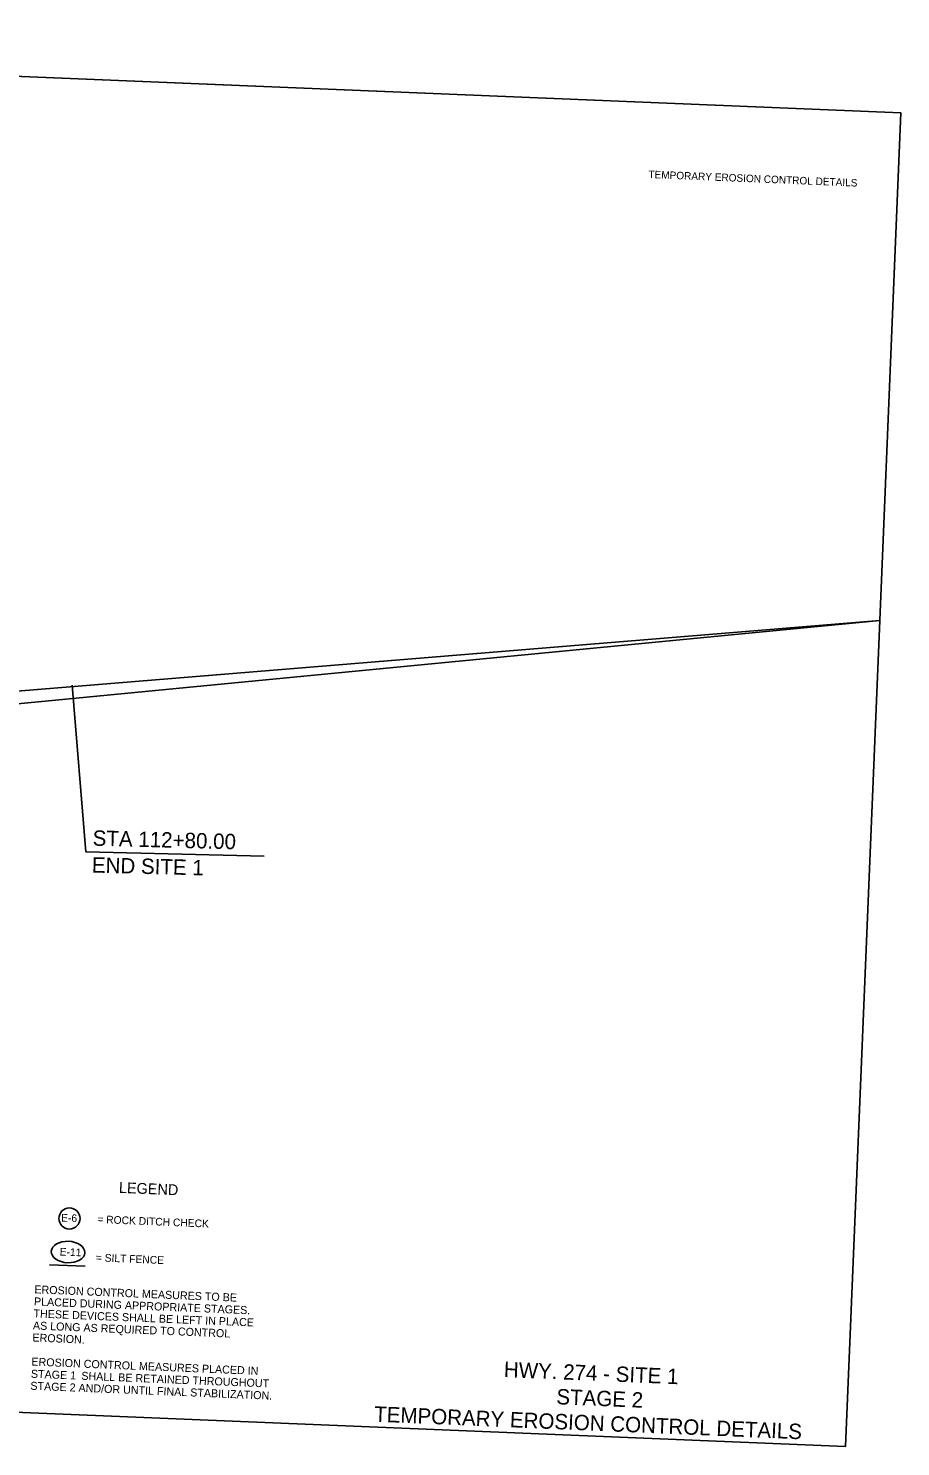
# Model space of a CAD drawing. Extents: x 1141828 to 1143465, y 1657046 to 1658153.
# Drawn here: x 1142784 to 1143465, y 1657046 to 1658153 of the extents above; entities that cross this region are included whole.
import ezdxf

# ---------------------------------------------------------------- set-up
doc = ezdxf.new("R2010")
doc.units = 0
for name, color, linetype in [('R_Annotation', 7, 'Continuous'), ('R_Border', 7, 'Continuous'), ('R_Erosion', 7, 'Continuous'), ('R_No Plot', 7, 'Continuous')]:
    doc.layers.add(name, color=color, linetype=linetype)

msp = doc.modelspace()

# ---------------------------------------------------------------- linework, layer by layer
at = {"layer": 'R_Annotation'}
for q in [(1142818.2, 1657640.2), (1142968, 1657506.6)]:
    msp.add_line((1142828.8, 1657510.1), q, dxfattribs=at)
at = {"layer": 'R_Erosion'}
msp.add_lwpolyline([(1142800.5, 1657187.6), (1142828.2, 1657186.5)], dxfattribs=at)
msp.add_circle((1142816, 1657223.8), 8.26, dxfattribs=at)
msp.add_ellipse((1142814.9, 1657197.6), major_axis=(13.1, -0.5), ratio=0.638788, dxfattribs=at)
at = {"layer": 'R_No Plot'}
for p, q in [((1143448.8, 1657690.7), (1142604.7, 1657621.7)), ((1143448.8, 1657690.6), (1142604.7, 1657621.6)), ((1143448.8, 1657690.7), (1142605.7, 1657609.2))]:
    msp.add_line(p, q, dxfattribs=at)
for points in [[(1141848.7, 1657609.9), (1141871.2, 1658153), (1143465.2, 1658087.1), (1143448.8, 1657690.7)], [(1142226.9, 1657603.3), (1142249.6, 1658137.4), (1143465.2, 1658087.1), (1143448.8, 1657690.7)], [(1141848.7, 1657609.8), (1141828.1, 1657111.6), (1143422.1, 1657045.7), (1143448.8, 1657690.6)]]:
    msp.add_lwpolyline(points, dxfattribs=at)

# ---------------------------------------------------------------- texts
at = {"layer": 'R_Annotation'}
for s, height, rotation, p in [('STA 112+80.00', 12, 358.5346, (1142834, 1657514.9)), ('END SITE 1', 12, 358.5346, (1142833.4, 1657493.9)), ('= ROCK DITCH CHECK', 6, 357.6311, (1142837.7, 1657220.3)), ('= SILT FENCE', 6, 357.6311, (1142836.5, 1657190.4)), ('EROSION CONTROL MEASURES TO BE', 6.25, 357.6311, (1142788.5, 1657165.4)), ('PLACED DURING APPROPRIATE STAGES. ', 6.25, 357.6311, (1142788.2, 1657156)), ('AS LONG AS REQUIRED TO CONTROL ', 6.25, 357.6311, (1142787.4, 1657137.2)), ('THESE DEVICES SHALL BE LEFT IN PLACE ', 6.25, 357.6311, (1142787.8, 1657146.6)), ('EROSION.', 6.25, 357.6311, (1142787, 1657127.8)), ('EROSION CONTROL MEASURES PLACED IN ', 6.25, 357.6311, (1142786.2, 1657109)), ('HWY. 274 - SITE 1', 12, 357.6311, (1143155.1, 1657100)), ('STAGE 1 ', 6.25, 357.6311, (1142785.8, 1657099.5)), ('SHALL BE RETAINED THROUGHOUT ', 6.25, 357.6311, (1142825.2, 1657097.9)), ('STAGE 2 AND/OR UNTIL FINAL STABILIZATION.', 6.25, 357.6311, (1142785.4, 1657090.1)), ('STAGE 2', 12, 357.6311, (1143196.1, 1657078.8)), ('TEMPORARY EROSION CONTROL DETAILS', 12, 357.6311, (1143053.8, 1657065.2))]:
    msp.add_text(s, height=height, rotation=rotation, dxfattribs=at).set_placement(p)
at = {"layer": 'R_Border'}
msp.add_text('TEMPORARY EROSION CONTROL DETAILS', height=5.862, rotation=357.6311, dxfattribs=at).set_placement((1143268.1, 1658036.2))
at = {"layer": 'R_Erosion'}
for s, height, rotation, p in [('LEGEND', 8.44, 357.6311, (1142854.5, 1657243.8)), ('E-6 ', 6, 358.0317, (1142809.4, 1657221.4)), ('E-11', 6, 357.8455, (1142808.3, 1657194.9))]:
    msp.add_text(s, height=height, rotation=rotation, dxfattribs=at).set_placement(p)

doc.saveas('drawing.dxf')
